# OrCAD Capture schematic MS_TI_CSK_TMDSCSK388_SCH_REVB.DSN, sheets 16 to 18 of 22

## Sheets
16 16.PMIC POWER 1: size C; title: PMIC POWER 1
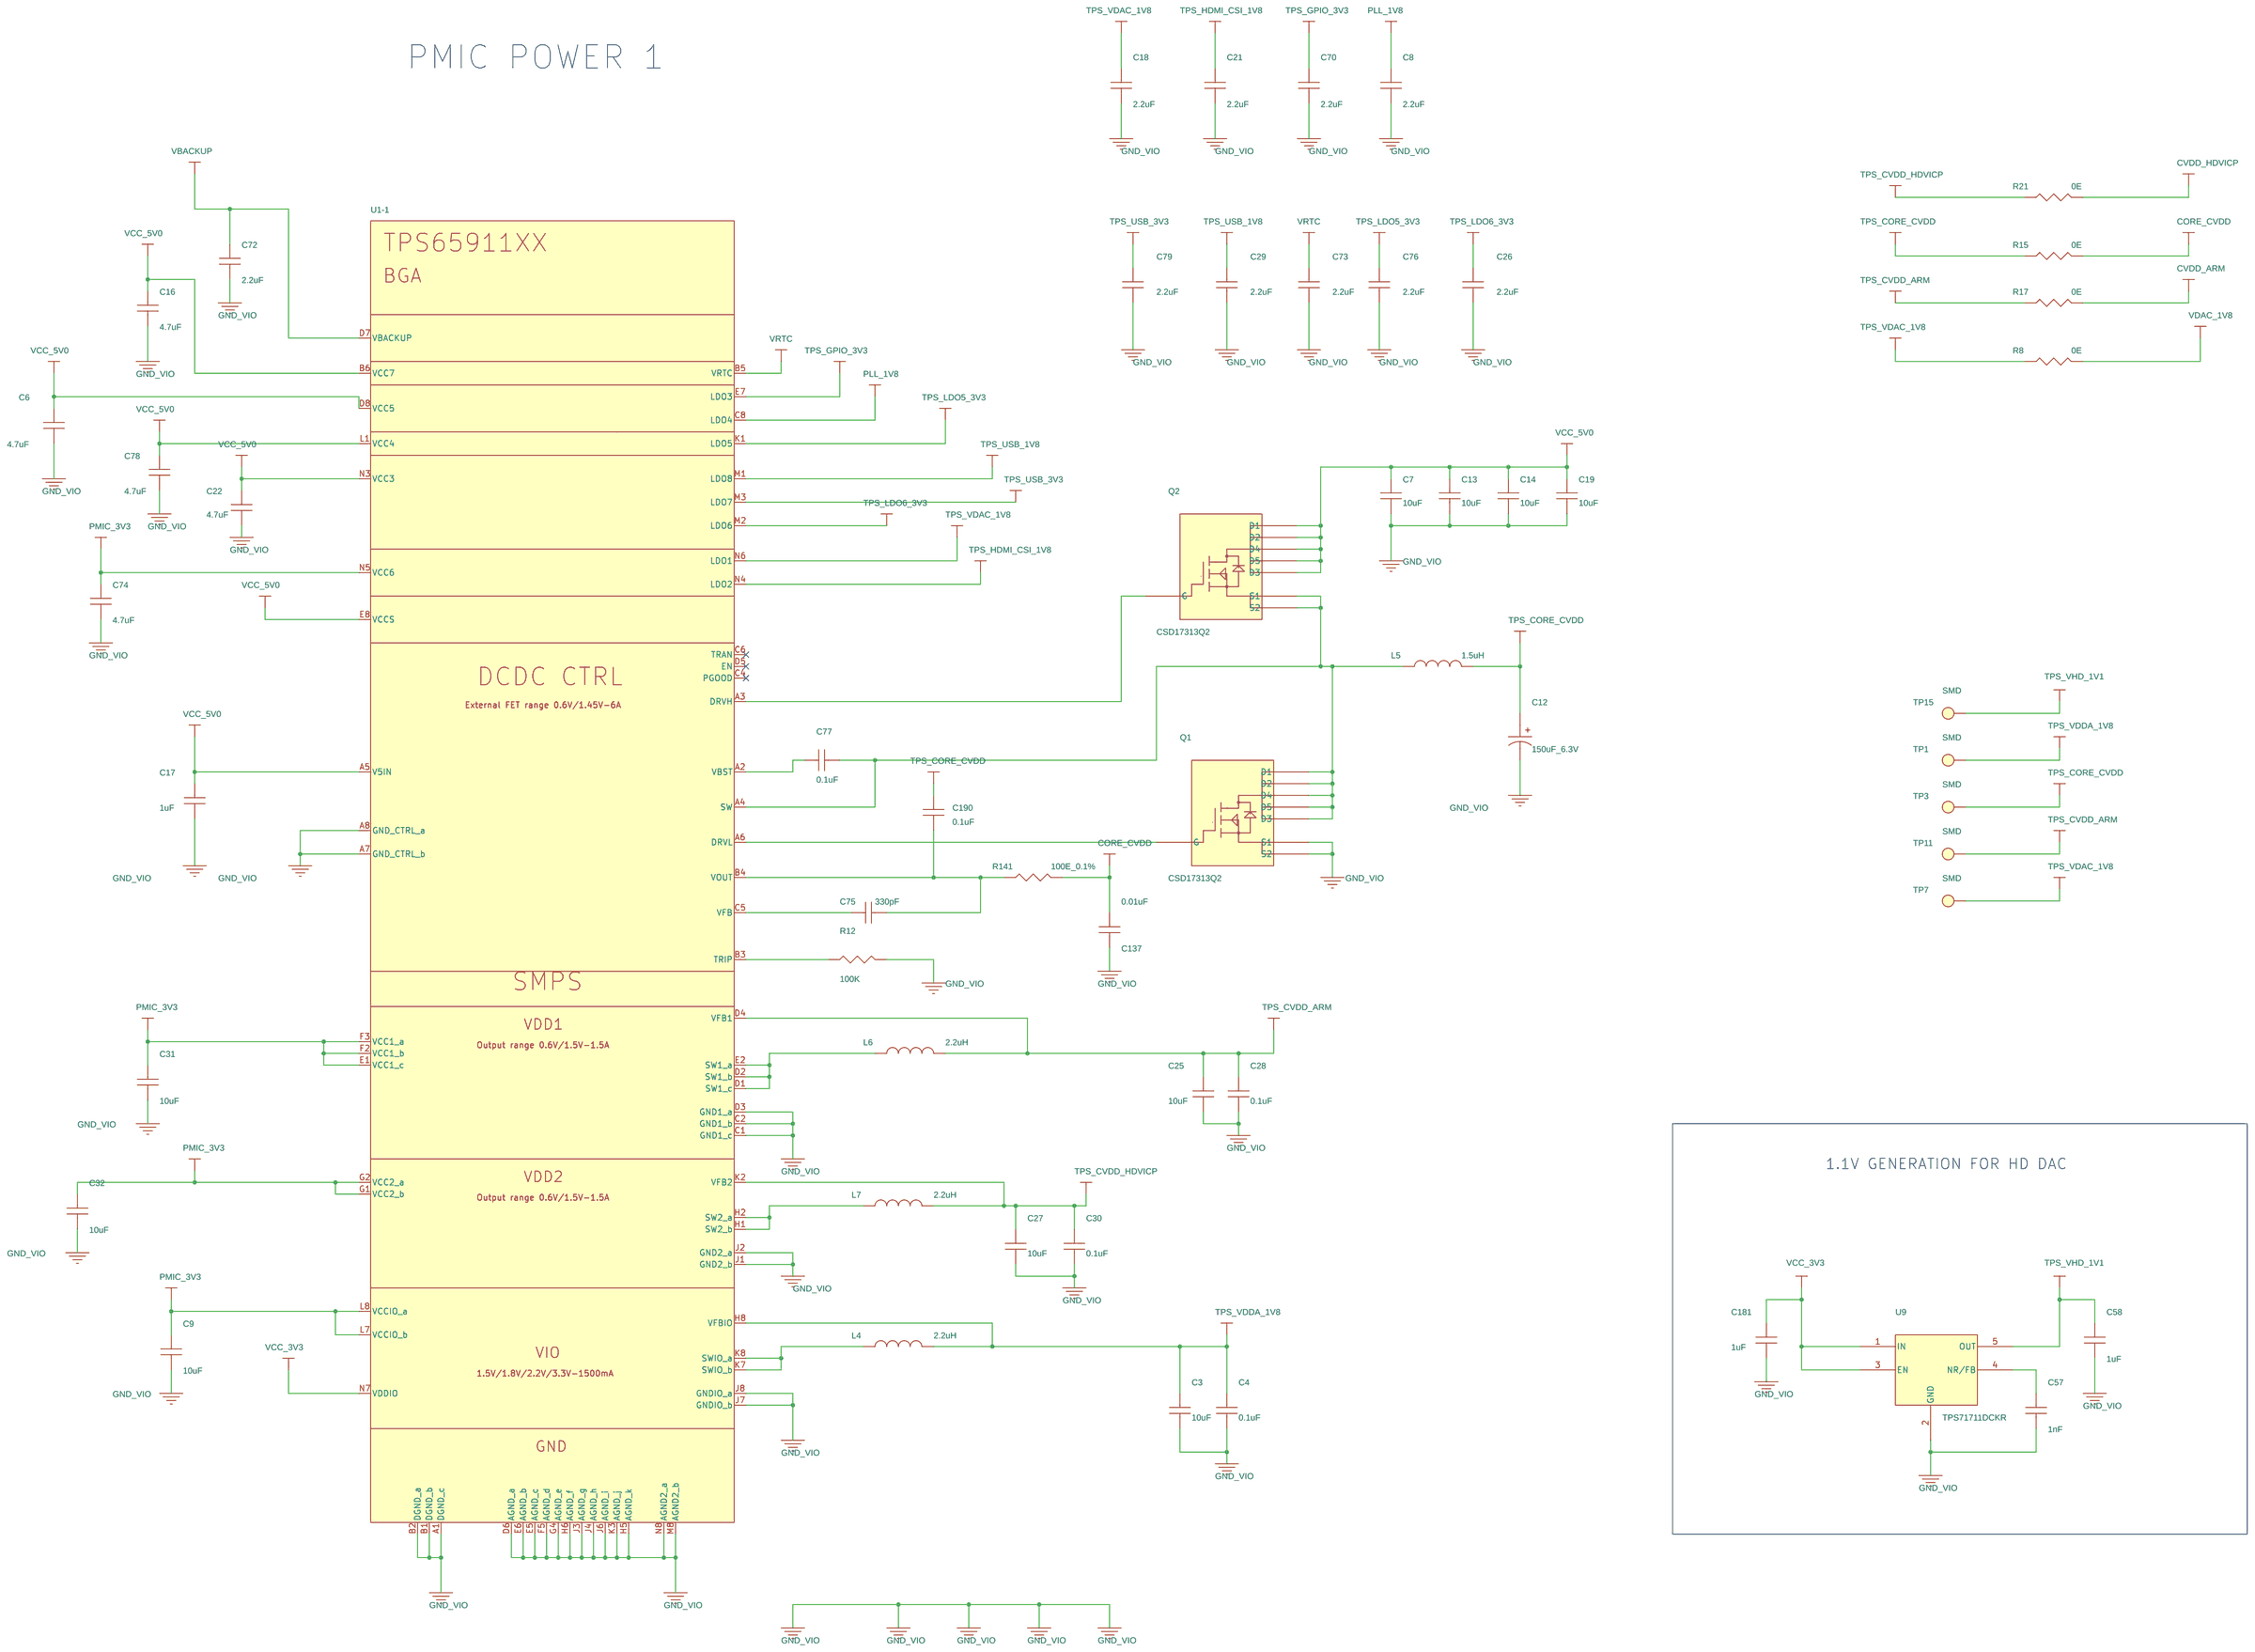
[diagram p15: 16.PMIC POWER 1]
17 17.PMIC POWER 2: size C; title: PMIC POWER 2
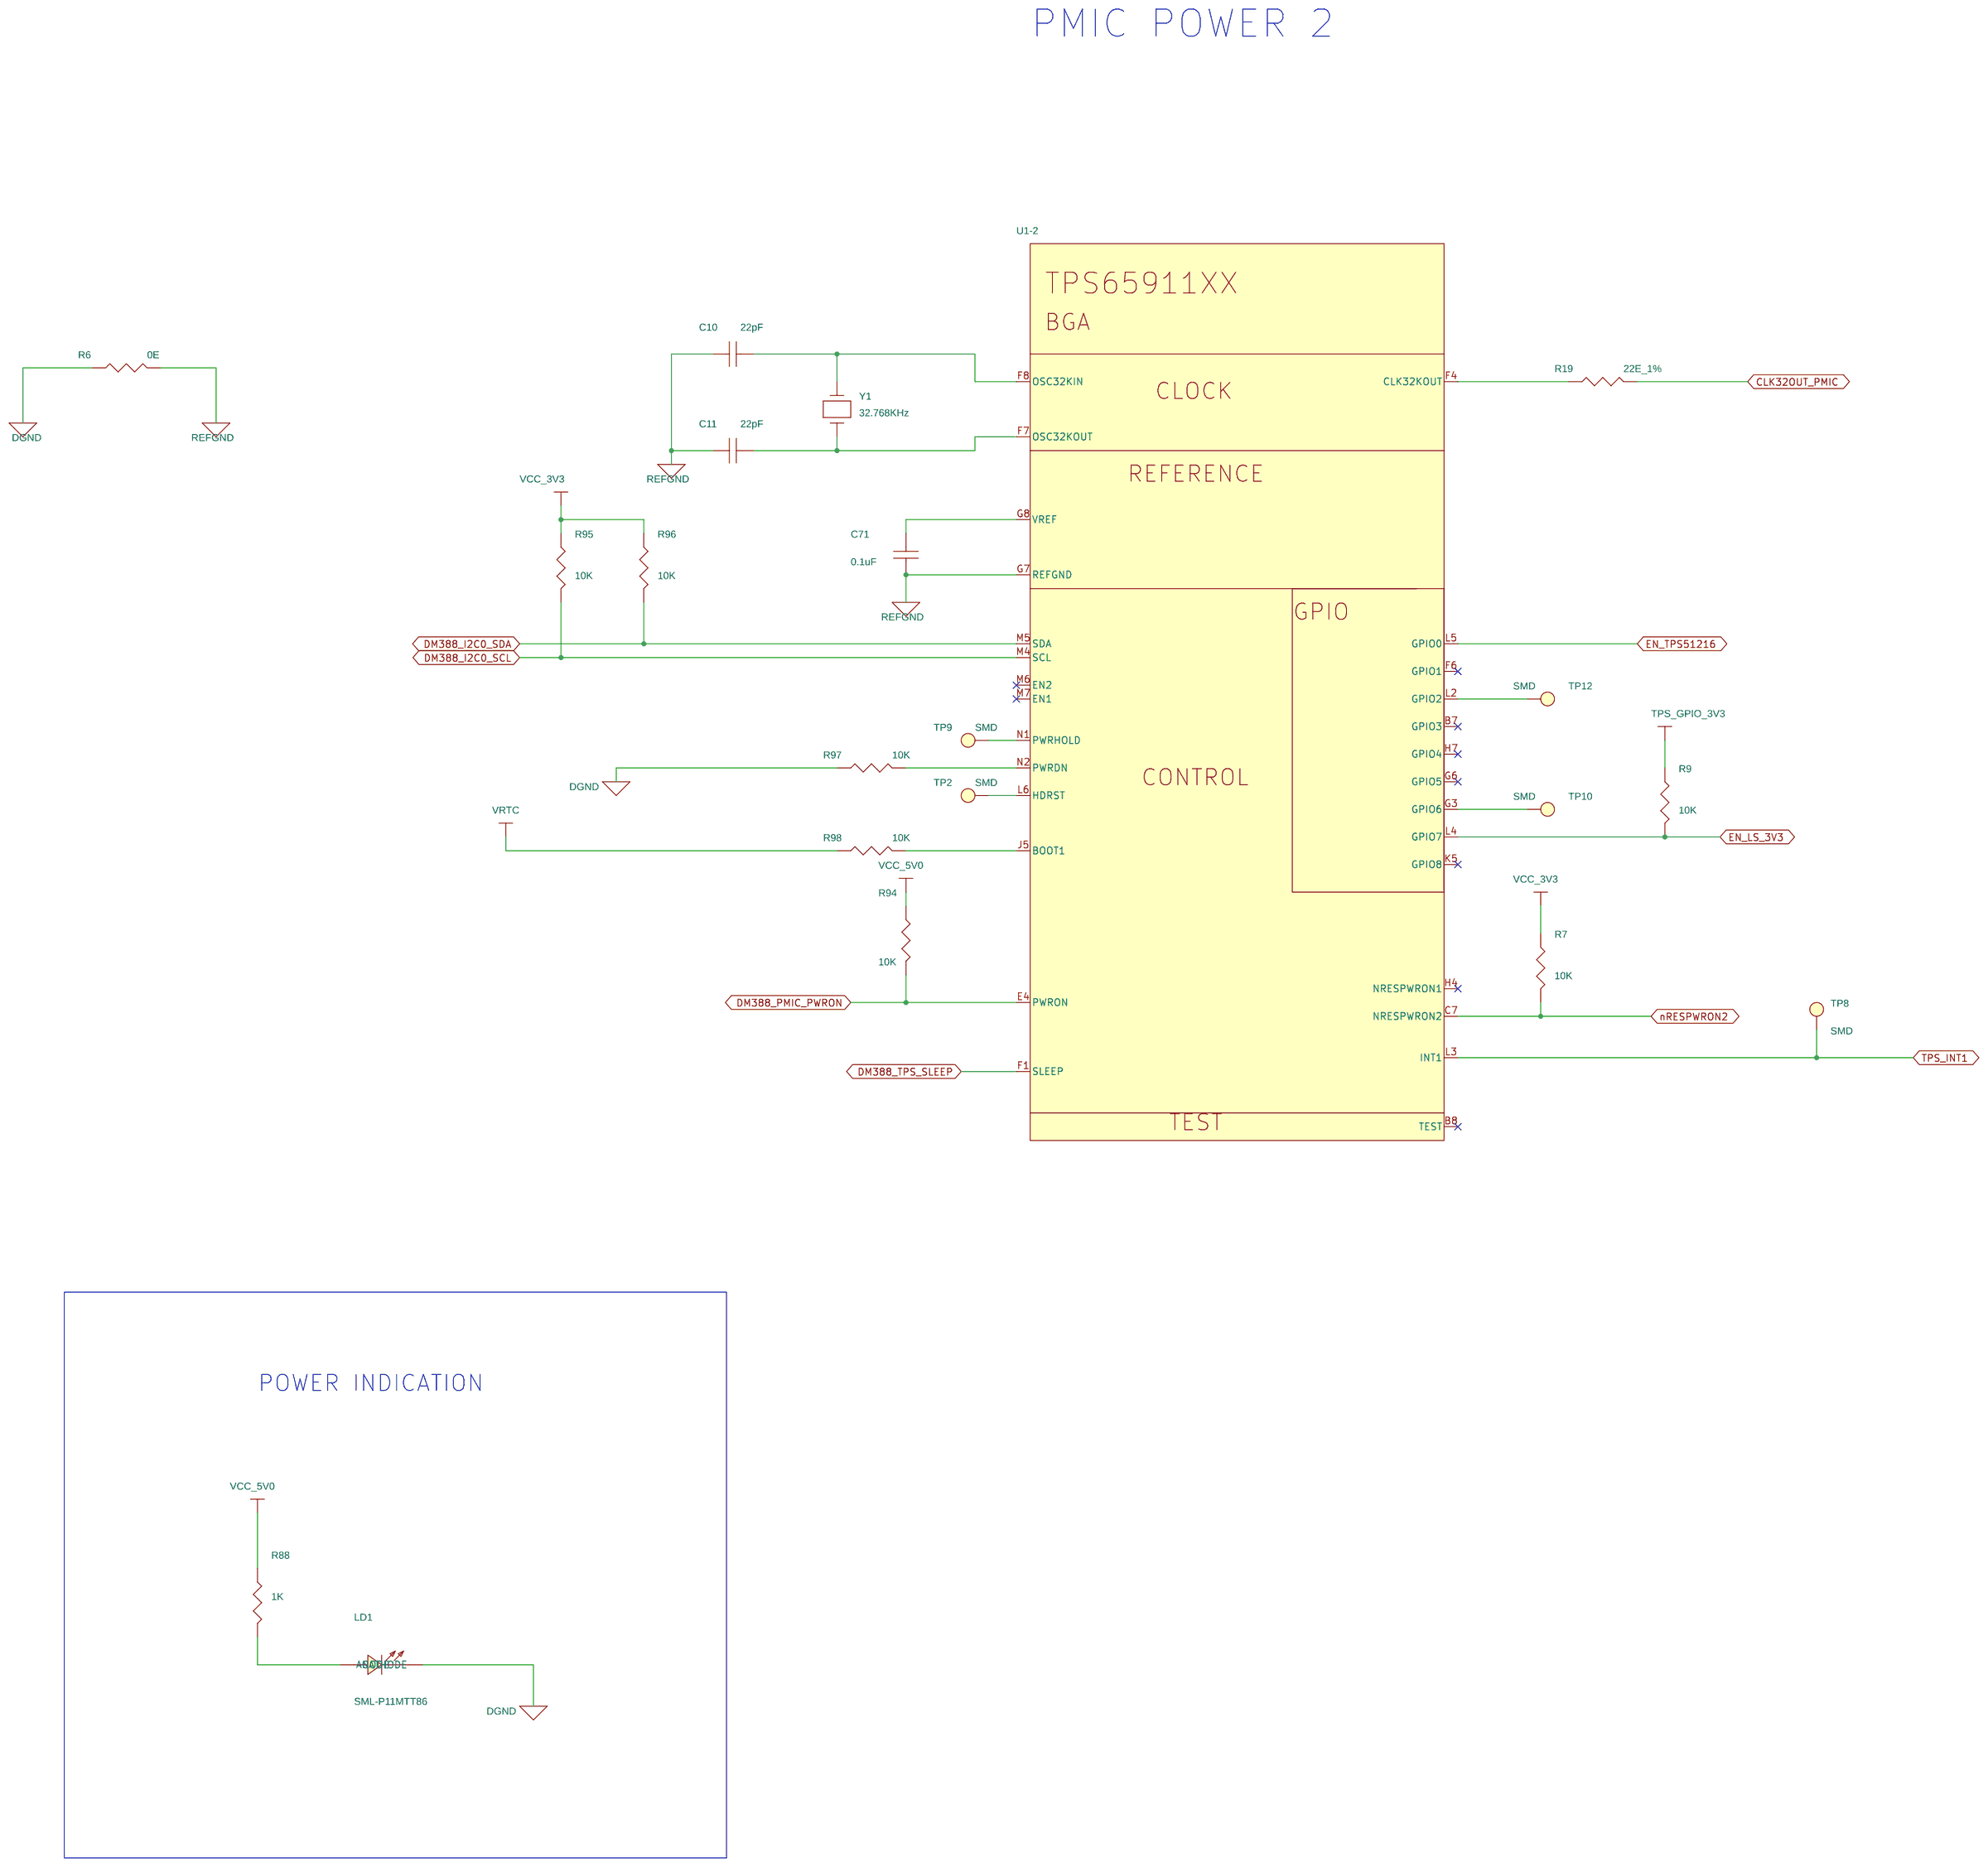
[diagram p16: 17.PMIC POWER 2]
18 18.DDR3 POWER: size C; title: DDR3 POWER
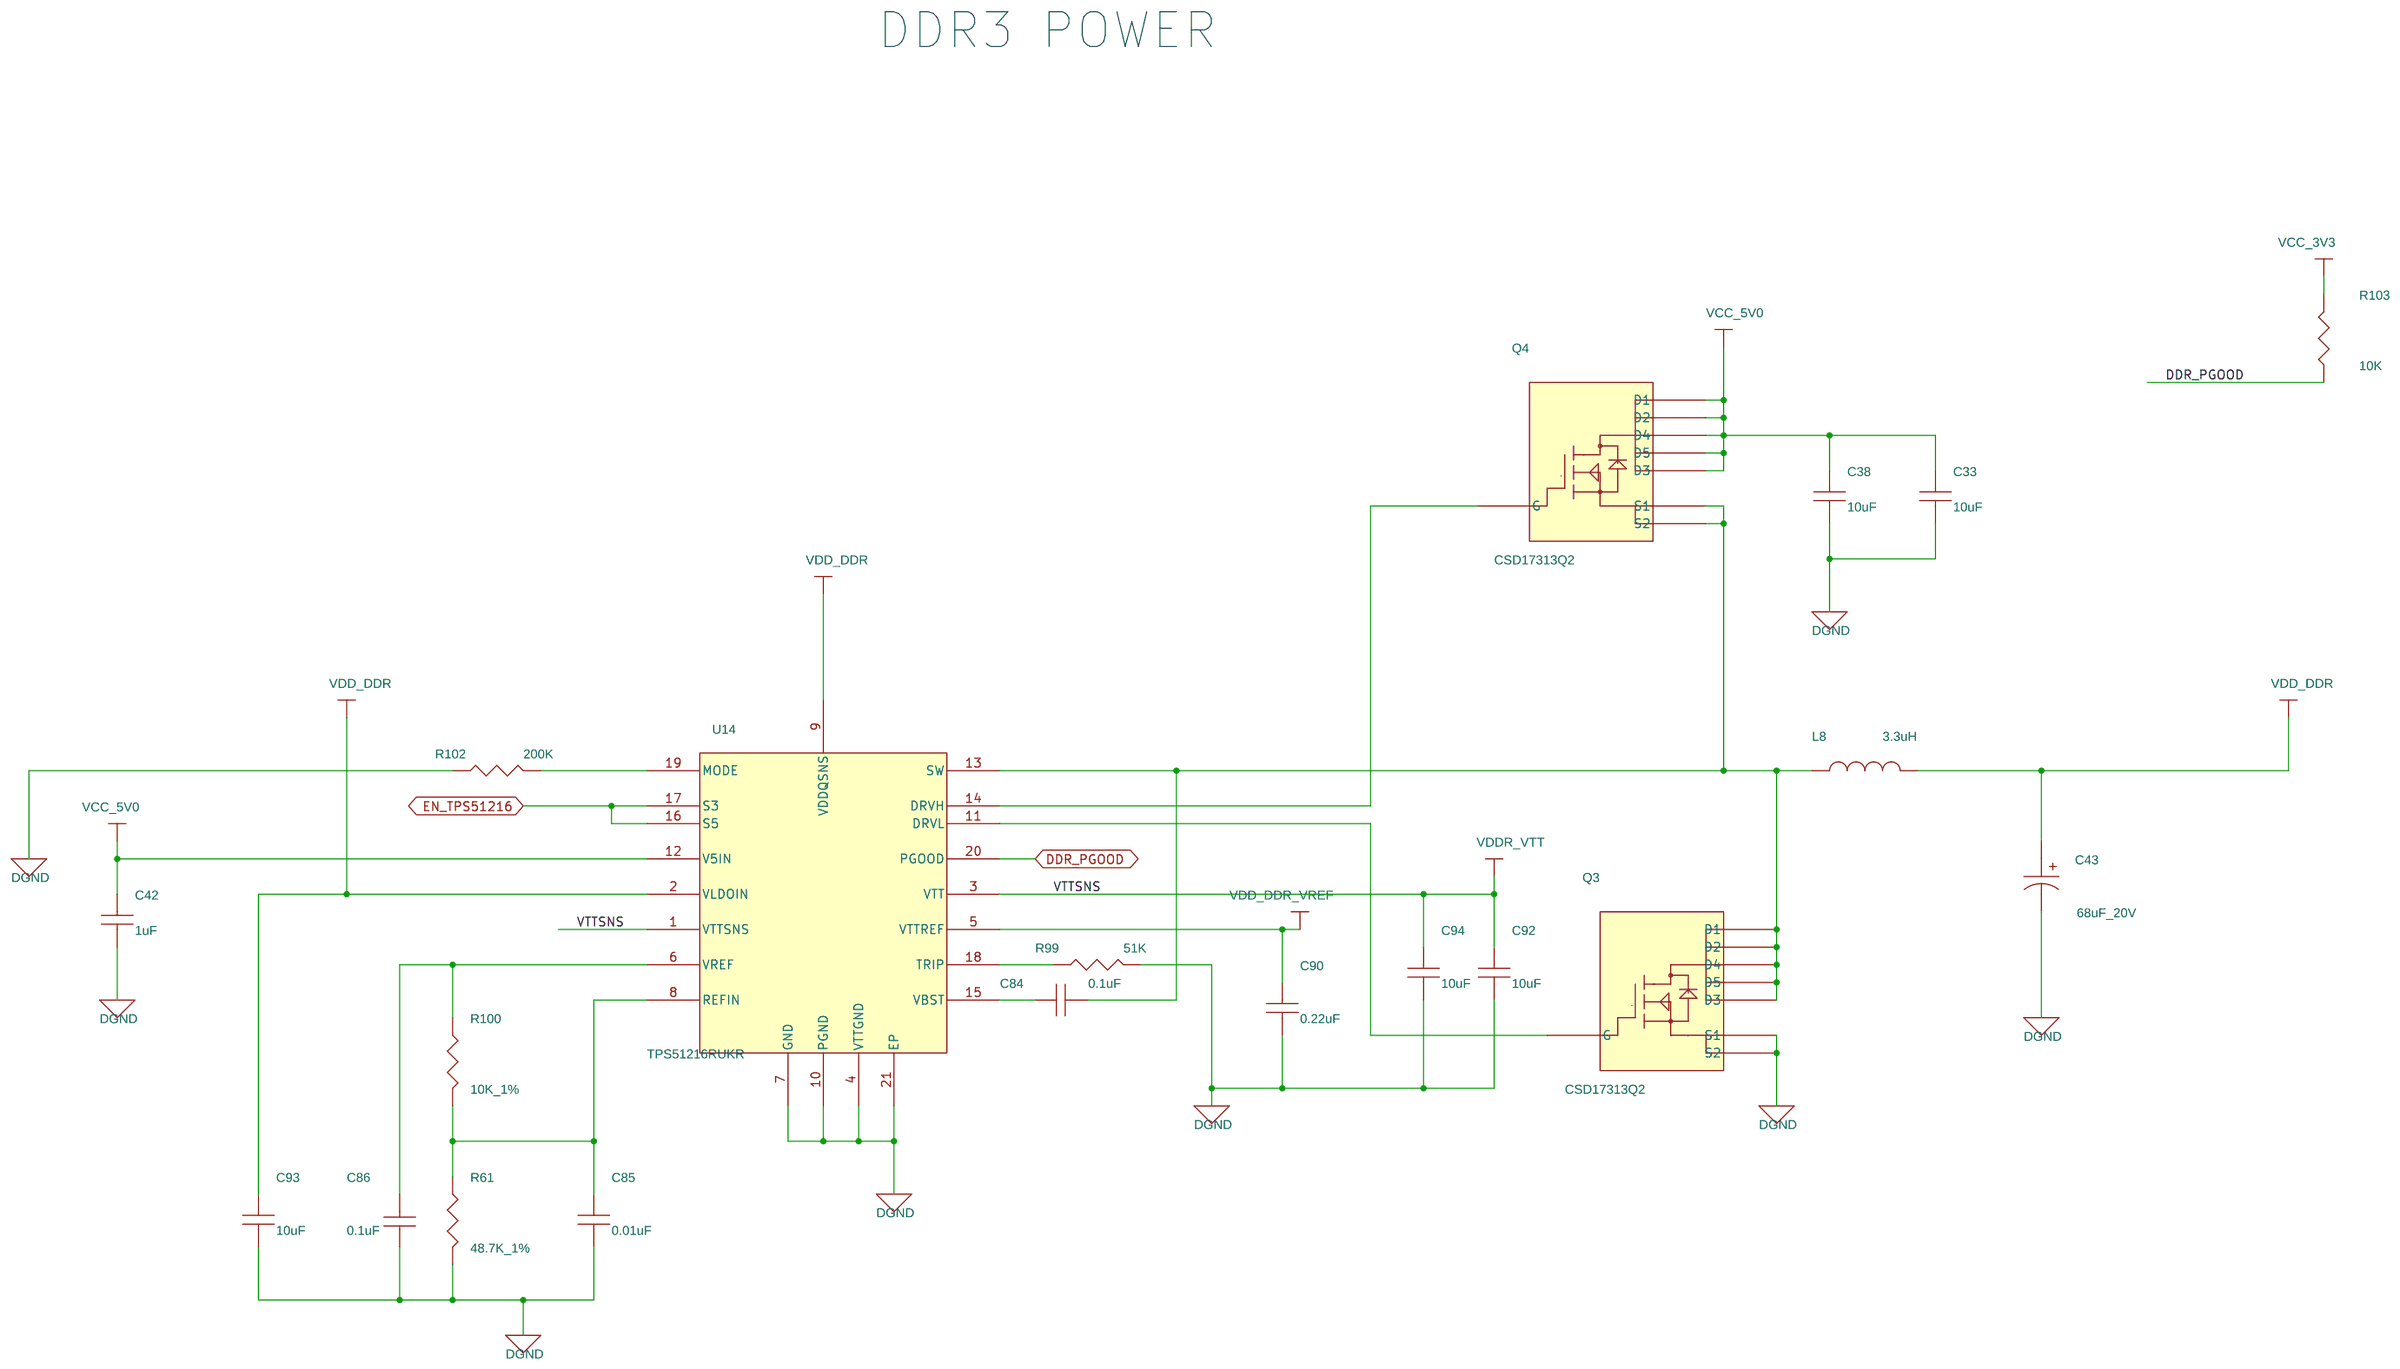
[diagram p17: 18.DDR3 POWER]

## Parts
sheet 16.PMIC POWER 1
C3  10uF  [CAP0402]
C4  0.1uF  [CAP0402]
C6  4.7uF  [CAP0603]
C7  10uF  [CAP0603]
C8  2.2uF  [CAP0402]
C9  10uF  [CAP0603]
C12  150uF_6.3V  [CAPT7343X]
C13  10uF  [CAP0603]
C14  10uF  [CAP0603]
C16  4.7uF  [CAP0603]
C17  1uF  [CAP0603]
C18  2.2uF  [CAP0402]
C19  10uF  [CAP0603]
C21  2.2uF  [CAP0402]
C22  4.7uF  [CAP0603]
C25  10uF  [CAP0402]
C26  2.2uF  [CAP0402]
C27  10uF  [CAP0402]
C28  0.1uF  [CAP0402]
C29  2.2uF  [CAP0402]
C30  0.1uF  [CAP0402]
C31  10uF  [CAP0603]
C32  10uF  [CAP0603]
C57  1nF  [CAP0402]
C58  1uF  [CAP0402]
C70  2.2uF  [CAP0402]
C72  2.2uF  [CAP0603]
C73  2.2uF  [CAP0402]
C74  4.7uF  [CAP0402]
C75  330pF  [CAP0402]
C76  2.2uF  [CAP0402]
C77  0.1uF  [CAP0402]
C78  4.7uF  [CAP0603]
C79  2.2uF  [CAP0402]
C137  0.01uF  [CAP0201]
C181  1uF  [CAP0402]
C190  0.1uF  [CAP0201]
L4  2.2uH  [IND_VLS252012HBX_110X90_SMD]
L5  1.5uH  [IND_XAL4030_170X170_SMD]
L6  2.2uH  [IND_VLS252012HBX_110X90_SMD]
L7  2.2uH  [IND_VLS252012HBX_110X90_SMD]
Q1  CSD17313Q2  [SON6_CSD17313Q2_80X80]
Q2  CSD17313Q2  [SON6_CSD17313Q2_80X80]
R8  0E  [RES0402]
R12  100K  [RES0402]
R15  0E  [RES0805]
R17  0E  [RES0402]
R21  0E  [RES0402]
R141  100E_0.1%  [RES0402]
TP1  SMD  [TP40_SMD]
TP3  SMD  [TP40_SMD]
TP7  SMD  [TP40_SMD]
TP11  SMD  [TP40_SMD]
TP15  SMD  [TP40_SMD]
U1  TPS6591133A2ZRCR  [BGA98_25-59_360x240]  (sections -1,-2)
U9  TPS71711DCKR  [SC70-5]
sheet 17.PMIC POWER 2
C10  22pF  [CAP0402]
C11  22pF  [CAP0402]
C71  0.1uF  [CAP0402]
LD1  SML-P11MTT86  [LED_0402]
R6  0E  [RES0402]
R7  10K  [RES0402]
R9  10K  [RES0402]
R19  22E_1%  [RES0402]
R88  1K  [RES0402]
R94  10K  [RES0402]
R95  10K  [RES0402]
R96  10K  [RES0402]
R97  10K  [RES0402]
R98  10K  [RES0402]
TP2  SMD  [TP40_SMD]
TP8  SMD  [TP40_SMD]
TP9  SMD  [TP40_SMD]
TP10  SMD  [TP40_SMD]
TP12  SMD  [TP40_SMD]
Y1  32.768KHz  [XTAL_9HT10_130X60_SMD]
sheet 18.DDR3 POWER
C33  10uF  [CAP0603]
C38  10uF  [CAP0603]
C42  1uF  [CAP0402]
C43  68uF_20V  [CAPT7343D]
C84  0.1uF  [CAP0402]
C85  0.01uF  [CAP0402]
C86  0.1uF  [CAP0402]
C90  0.22uF  [CAP0402]
C92  10uF  [CAP0402]
C93  10uF  [CAP0402]
C94  10uF  [CAP0402]
L8  3.3uH  [IND_NRS5020_200x200_SMD]
Q3  CSD17313Q2  [SON6_CSD17313Q2_80X80]
Q4  CSD17313Q2  [SON6_CSD17313Q2_80X80]
R61  48.7K_1%  [RES0402]
R99  51K  [RES0402]
R100  10K_1%  [RES0402]
R102  200K  [RES0402]
R103  10K  [RES0402]
U14  TPS51216RUKR  [QFN20_15-74_120X120]

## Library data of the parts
C3 C25 C27 C92-C94 = CAP: CAP CERAMIC 10uF 6.3V 20% X5R 0402; Chkd/date: VASANTHA/120516; Crtd /date: VASANTHA/120516; Custom_Duty: 15%; Customs_HS_Code: 85322990; Distributor_name: DIGIKEY; Distributor_part_number: 1276-1451-1-ND; Height: 0.55MM; Mfr_name: SAMSUNG ELECTRO MECHANIC; Mfr_part_number: CL05A106MQ5NUNC; Mistral Part No: 120014120008-R; Package: 0402; Part_type: CAPACITORS\CERAMIC; Project: TMDXCSK368; RoHS: RoHS; Temperature: -55°C+85°C; Tolerance: 20%; Voltage: 6.3V; Wattage: NA; Weight: NA; Datasheet: Y:\MIS_DATABASE\DATASHEETS\CAPACITORS\CL_SERIES.PDF
C4 C28 C30 C77 C84 C86 = CAP: CAP CERAMIC 0.1uF 16V 10% X7R 0402; Alternate_mfr_name_A: KEMET; Alternate_mfr_part_number_A: C0402C104K4RACT; Chkd/date: MAZHAR/281108; Crtd /date: MAZHAR/030907; Cust_part_number: 1500-80042E; Custom_Duty: 15%; Customs_HS_Code: 85322990; Distributor_name: DIGIKEY; Distributor_name_A: DIGIKEY; Distributor_part_number: 490-3261-1-ND; Distributor_part_number_A: 399-3521-1-ND; Height: 0.55MM; Mfr_name: MURATA; Mfr_part_number: GRM155R71C104KA88D; Mistral Part No: 120009030060-R; Package: 0402; Part_type: CAPACITORS\CERAMIC; Project: SMART VIEW_IP CAMERA; Tolerance: 10%; Voltage: 16V; Wattage: NA; Weight: NA; Datasheet: Y:\MIS_DATABASE\DATASHEETS\CAPACITORS\GRM188SERIES.PDF
C6 C16 C22 C78 = CAP: CAP CERAMIC 4.7uF 16V 10% X5R 0603; Chkd/date: VASANTHA/230714; Crtd /date: BAVISH/060511; Custom_Duty: 15%; Customs_HS_Code: 85322990; Distributor_name: DIGIKEY; Distributor_part_number: 587-2786-1-ND; Height: 0.90MM; Mfr_name: TAIYO YUDEN; Mfr_part_number: EMK107ABJ475KA-T; Mistral Part No: 120011050004-R; Package: 0603; Part_type: CAPACITORS\CERAMIC; Project: HMC; RoHS: RoHS; Temperature: -55°C+85°C; Tolerance: 10%; Voltage: 16V; Wattage: NA; Weight: NA; Datasheet: Y:\MIS_DATABASE\DATASHEETS\CAPACITORS\EMK107.PDF
C7 C13 C14 C19 C33 C38 = CAP: CAP CERAMIC 10uF 16V 20% X5R 0603; Chkd/date: USMAN/060114; Crtd /date: USMAN/151013; Custom_Duty: 15%; Customs_HS_Code: 85322990; Distributor_name: DIGIKEY; Distributor_part_number: 490-7201-1-ND; Height: 0.90MM; Mfr_name: MURATA; Mfr_part_number: GRM188R61C106MA73D; Mistral Part No: 120013100015-R; Package: 0603; Part_type: CAPACITORS\CERAMIC; Project: C-BAND_SYNTH; RoHS: RoHS; Temperature: -55°C+85°C; Tolerance: 20%; Voltage: 16V; Wattage: NA; Weight: NA; Datasheet: Y:\MIS_DATABASE\DATASHEETS\CAPACITORS\GRM188SERIES.PDF
C8 C18 C21 C26 C29 C70 C73 C76 C79 = CAP: CAP CERAMIC 2.2uF 10V 10% X5R 0402; Chkd/date: VASANTHA/120516; Crtd /date: VASANTHA/120516; Custom_Duty: 15%; Customs_HS_Code: 85322990; Distributor_name: DIGIKEY; Distributor_part_number: 1276-1462-1-ND; Height: 0.55MM; Mfr_name: SAMSUNG ELECTRO MECHANIC; Mfr_part_number: CL05A225KP5NNNC; Mistral Part No: 120011100038-R; Package: 0402; Part_type: CAPACITORS\CERAMIC; Project: TMDXCSK368; RoHS: RoHS; Temperature: -55°C+85°C; Tolerance: 10%; Voltage: 10V; Wattage: NA; Weight: NA; Datasheet: Y:\MIS_DATABASE\DATASHEETS\CAPACITORS\CL_SERIES.PDF
C9 C31 C32 = CAP: CAP CERAMIC 10uF 10V 20% X5R 0603; Chkd/date: VASANTHA/120516; Crtd /date: VASANTHA/120516; Custom_Duty: 15%; Customs_HS_Code: 85322990; Distributor_name: DIGIKEY; Distributor_part_number: 490-10475-1-ND; Height: 0.90MM; Mfr_name: MURATA; Mfr_part_number: GRM188R61A106ME69D; Mistral Part No: 120009050022-R; Package: 0603; Part_type: CAPACITORS\CERAMIC; Project: TMDXCSK368; RoHS: RoHS; Temperature: -55°C+85°C; Tolerance: 20%; Voltage: 10V; Wattage: NA; Weight: NA; Datasheet: Y:\MIS_DATABASE\DATASHEETS\CAPACITORS\GRM188SERIES.PDF
C12 = CAP_POL: CAP TANTALUM 150uF 6.3V 20% ESR 15mE D7343; Chkd/date: MAZHAR/230806; Crtd /date: ARAVIND/10/08/06; Custom_Duty: 15%; Customs_HS_Code: 85322990; Distributor_name: DIGIKEY; Distributor_part_number: 399-3055-1-ND; Height: 4.30MM; Mfr_name: KEMET; Mfr_part_number: A700X157M006ATE015; Mistral Part No: 120009030654; Package: D7343; Part_type: CAPACITORS\TANTALUM; Project: PMF BASE CARD; Tolerance: 20%; Voltage: 6.3V; Datasheet: Y:\MIS_DATABASE\DATASHEETS\CAPACITORS\A700X157M006ATE015.PDF
C17 = CAP: CAP CERAMIC 1uF 25V 10% X7R 0603; Chkd/date: VASANTHA/120516; Crtd /date: VASANTHA/120516; Custom_Duty: 15%; Customs_HS_Code: 85322990; Distributor_name: DIGIKEY; Distributor_part_number: 1276-1184-1-ND; Height: 0.90MM; Mfr_name: SAMSUNG ELECTRO MECHANIC; Mfr_part_number: CL10B105KA8NNNC; Mistral Part No: 120011010017-R; Package: 0603; Part_type: CAPACITORS\CERAMIC; Project: TMDXCSK368; RoHS: RoHS; Temperature: -55°C+125°C; Tolerance: 10%; Voltage: 25V; Wattage: NA; Weight: NA; Datasheet: Y:\MIS_DATABASE\DATASHEETS\CAPACITORS\CL_SERIES.PDF
C57 = CAP: CAP CERAMIC 1nF 50V 5% X7R 0402; Chkd/date: BAVISH/100611; Crtd /date: BAVISH/090611; Custom_Duty: 15%; Customs_HS_Code: 85322990; Distributor_name: DIGIKEY; Distributor_part_number: 478-3661-1-ND; Height: 0.60MM; Mfr_name: AVX CORPORATION; Mfr_part_number: 04025C102JAT2A; Mistral Part No: 120011060017-R; Package: 0402; Part_type: CAPACITORS\CERAMIC; Project: CENTAURUS_LCD-ADAPTER; RoHS: RoHS; Temperature: -55°C+125°C; Tolerance: 5%; Voltage: 50V; Wattage: NA; Weight: NA; Datasheet: Y:\MIS_DATABASE\DATASHEETS\CAPACITORS\AVX_MLC.PDF
C42 C58 C181 = CAP: CAP CERAMIC 1uF 10V 10% X5R 0402; Chkd/date: SHREESHAIL/290507; Crtd /date: MAZHAR/290806; Custom_Duty: 15%; Customs_HS_Code: 85322990; Distributor_name: DIGIKEY; Distributor_part_number: 490-3890-1-ND; Height: 0.55MM; Mfr_name: MURATA; Mfr_part_number: GRM155R61A105KE15D; Mistral Part No: 120009030264; Package: 0402; Part_type: CAPACITORS\CERAMIC; Project: SVDO_RMB_MMA; Tolerance: 10%; Voltage: 10V; Datasheet: Y:\MIS_DATABASE\DATASHEETS\CAPACITORS\GRM188SERIES.PDF
C72 = CAP: CAP CERAMIC 2.2uF 16V 10% X5R 0603; Chkd/date: VASANTHA/120516; Crtd /date: VASANTHA/120516; Custom_Duty: 15%; Customs_HS_Code: 85322990; Distributor_name: DIGIKEY; Distributor_part_number: 490-3296-1-ND; Height: 0.90MM; Mfr_name: MURATA; Mfr_part_number: GRM188R61C225KE15D; Mistral Part No: 120009050002-R; Package: 0603; Part_type: CAPACITORS\CERAMIC; Project: TMDXCSK368; RoHS: RoHS; Temperature: -55°C+85°C; Tolerance: 10%; Voltage: 16V; Wattage: NA; Weight: NA; Datasheet: Y:\MIS_DATABASE\DATASHEETS\CAPACITORS\GRM188SERIES.PDF
C74 = CAP: CAP CERAMIC 4.7uF 10V 10% X5R 0402; Chkd/date: VASANTHA/171014; Crtd /date: NAVEED/200814; Custom_Duty: 15%; Customs_HS_Code: 85322990; Distributor_name: DIGIKEY; Distributor_part_number: 445-13820-1-ND; Height: 0.55MM; Mfr_name: TDK CORPORATION; Mfr_part_number: C1005X5R1A475K050BC; Mistral Part No: 120014080006-R; Package: 0402; Part_type: CAPACITORS\CERAMIC; Project: HUMANWARE PHONEIX; RoHS: RoHS; Temperature: -55°C+85°C; Tolerance: 10%; Voltage: 10V; Wattage: NA; Weight: NA; Datasheet: Y:\MIS_DATABASE\DATASHEETS\CAPACITORS\C1005X5R1A475M.PDF
C75 = CAP: CAP CERAMIC 330pF 50V 5% NP0 0402; Chkd/date: SHREESHAIL/290507; Crtd /date: MAZHAR/221206; Custom_Duty: 15%; Customs_HS_Code: 85322990; Distributor_name: DIGIKEY; Distributor_part_number: 490-1295-1-ND; Height: 0.55MM; Mfr_name: MURATA; Mfr_part_number: GRM1555C1H331JA01D; Mistral Part No: 120009030375; Package: 0402; Part_type: CAPACITORS\CERAMIC; Project: ADR1B; Tolerance: 5%; Voltage: 50V; Datasheet: Y:\MIS_DATABASE\DATASHEETS\CAPACITORS\GRM188SERIES.PDF
C137 = CAP: CAP CERAMIC 0.01uF 10V 10% X7R 0201; Chkd/date: MAZHAR/301208; Crtd /date: MAZHAR/080306; Cust_part_number: 1500-80097E; Custom_Duty: 15%; Customs_HS_Code: 85322990; Distributor_name: DIGIKEY; Distributor_part_number: 490-3194-1-ND; Height: 0.33MM; Mfr_name: MURATA; Mfr_part_number: GRM033R71A103KA01D; Mistral Part No: 120009030029-R; Package: 0201; Part_type: CAPACITORS\CERAMIC; Project: J32; RoHS: RoHS; Tolerance: 10%; Voltage: 10V; Datasheet: Y:\MIS_DATABASE\DATASHEETS\CAPACITORS\GRM033.PDF
C190 = CAP: CAP CERAMIC 0.1uF 10V 20% X5R 0201; Chkd/date: RAGESH/290910; Crtd /date: MUDDU/290410; Custom_Duty: 15%; Customs_HS_Code: 85322990; Distributor_name: DIGIKEY; Distributor_part_number: 490-5405-1-ND; Height: 0.33MM; Mfr_name: MURATA; Mfr_part_number: GRM033R61A104ME15D; Mistral Part No: 120010040004-R; Package: 0201; Part_type: CAPACITORS\CERAMIC; Project: BUG_BASE-II; RoHS: RoHS; Temperature: -55°C+85°C; Tolerance: 20%; Voltage: 10V; Weight: NA; Datasheet: Y:\MIS_DATABASE\DATASHEETS\CAPACITORS\MURATA_CMCC.PDF
L4 L6 L7 = INDUCTOR: IND POWER 2.2uH 2.3A 20% SMD; Chkd/date: VASANTHA/250516; Crtd /date: VASANTHA/250516; Custom_Duty: 24%; Customs_HS_Code: 85437099; Distributor_name: DIGIKEY; Distributor_part_number: 445-173027-1-ND; Height: 1.20MM; Mfr_name: TDK CORPORATION; Mfr_part_number: VLS252012HBX-2R2M-1; Mistral Part No: 130016050036-R; Package: SMD; Project: TMDXCSK388; RoHS: RoHS; Temperature: -40°C+105°C; Tolerance: 20%; Voltage: NA; Wattage: NA; Weight: NA; Datasheet: Y:\MIS_DATABASE\DATASHEETS\DISCRETES\INDUCTORS\VLS252012HBX.PDF
L5 = INDUCTOR: IND POWER 1.5uH 20% 7.5A SMD; Chkd/date: JEBRAN/060815; Crtd /date: JEBRAN/060815; Cust_part_number: 1800-80031E; Custom_Duty: 24%; Customs_HS_Code: 85437099; Distributor_name: MOUSER; Distributor_part_number: 994-XAL4020-152MEB; Height: 4.10MM; Mfr_name: COILCARFT; Mfr_part_number: XAL4020-152MEB; Mistral Part No: 130015080007-R; Package: SMD; Project: OCTASIC; RoHS: RoHS; Temperature: -40°C+125°C; Tolerance: 20%; Voltage: NA; Wattage: NA; Weight: 0.37g; Datasheet: Y:\MIS_DATABASE\DATASHEETS\DISCRETES\INDUCTORS\XAL4020.PDF
Q1-Q4 = MOSFET_CSD17313Q2: IC MOSFET N-CHANNEL SON6; Chkd/date: VASANTHA/291214; Crtd /date: NAVEED/110914; Custom_Duty: 15%; Customs_HS_Code: 85423100; Distributor_name: DIGIKEY; Distributor_part_number: 296-27233-1-ND; Height: 0.85MM; Mfr_name: TEXAS INSTRUMENTS; Mistral Part No: 142014090005-R; Package: SON6; Part_type: ICS\POWER\MOSFET; Project: ZK_BIOMETRIC; RoHS: RoHS; Temperature: -55°C+150°C; Tolerance: NA; Voltage: NA; Wattage: NA; Weight: NA; Datasheet: Y:\MIS_DATABASE\DATASHEETS\DISCRETES\TRANSISTORS_FETS\CSD17313Q2.PDF
R8 R17 R21 = RESISTOR: RES 0E 1/16W 5% 0402; Chkd/date: USMAN240712; Crtd /date: CHAITHANYA/300911; Custom_Duty: 15%; Customs_HS_Code: 85332119; Distributor_name: DIGIKEY; Distributor_part_number: 311-0.0JRCT-ND; Height: 0.40MM; Mfr_name: YAGEO; Mfr_part_number: RC0402JR-070RL; Mistral Part No: 110011090036-R; Package: 0402; Part_type: RESISTORS\FIXED; Project: VP-4000-PROCESSOR; RoHS: RoHS; SIGNAL_MODEL: RESISTOR_RES0402_0E_0E; Temperature: -55°C+155°C; Tolerance: 5%; Voltage: NA; Wattage: 1/16W; Weight: NA; Datasheet: Y:\MIS_DATABASE\DATASHEETS\RESISTORS\YAGEO_RC0402JR.PDF
R12 = RESISTOR: RES 100K 1/16W 5% 0402; Chkd/date: VASANTHA/130516; Crtd /date: VASANTHA/130516; Custom_Duty: 15%; Customs_HS_Code: 85332119; Distributor_name: DIGIKEY; Distributor_part_number: A121521CT-ND; Height: 0.40MM; Mfr_name: TE CONNECTIVITY; Mfr_part_number: CRG0402J100K/10; Mistral Part No: 110011060002-R; Package: 0402; Part_type: RESISTORS\FIXED; Project: TMDXCSK368; RoHS: RoHS; Temperature: -55°C+125°C; Tolerance: 5%; Voltage: NA; Wattage: 1/16W; Weight: NA; Datasheet: Y:\MIS_DATABASE\DATASHEETS\RESISTORS\CRG-SERIES.PDF
R15 = R: RES 0E 1/8W 5% 0805; Alternate_mfr_name_B: PANASONIC-ECG-ECG; Alternate_mfr_part_number_B: ERJ-6GEY0R00V; Chkd/date: MAZHAR/170709; Crtd /date: MAZHAR/181007; Cust_part_number: 4700-00000E; Custom_Duty: 15%; Customs_HS_Code: 85332119; Distributor_name: DIGIKEY; Distributor_name_B: DIGIKEY; Distributor_part_number: RHM0.0ACT-ND; Distributor_part_number_B: P0.0ACT-ND; Height: 0.70MM; Mfr_name: ROHM; Mfr_part_number: MCR10EZHJ000; Mistral Part No: 110009030074-R; Package: 0805; Part_type: RESISTORS\FIXED; Project: SD_WATERLOO; RoHS: RoHS; Tolerance: 5%; Wattage: 1/8W; Datasheet: Y:\MIS_DATABASE\DATASHEETS\RESISTORS\MCR10.PDF
R141 = RESISTOR: RES 100E 1/16W 0.1% 0402; Chkd/date: SUHAS/290910; Crtd /date: MUDDU/020910; Custom_Duty: 15%; Customs_HS_Code: 85332119; Distributor_name: DIGIKEY; Distributor_part_number: TNP100DACT-ND; Height: 0.40MM; Mfr_name: VISHAY; Mfr_part_number: TNPW0402100RBEED; Mistral Part No: 110010090013-P; Package: 0402; Part_type: RESISTORS\FIXED; Project: FLR PSPU; RoHS: Pb-Free; Temperature: -55°C+125°C; Tolerance: 0.1%; Voltage: 25V; Wattage: 1/16W; Weight: 0.65g/1000pcs; Datasheet: Y:\MIS_DATABASE\DATASHEETS\RESISTORS\VISHAY_TNPW_0.1%.PDF
TP1-TP3 TP7-TP12 TP15 = TESTPOINT: TESTPOINT 40 SMD; Chkd/date: MAZHAR/190505; Crtd /date: MAZHAR/190505; Distributor_name: NA; Distributor_part_number: NA; Height: NA; Mfr_name: LOCAL; Mistral Part No: 130009030933; Part_type: MISC\TESTPOINT; Project: RAINIER-3
U1 = TPS659113A2_BGA98: IC POWER MANAGEMENT BGA98; Chkd/date: VASANTHA/170516; Crtd /date: VASANTHA/170516; Custom_Duty: 15%; Customs_HS_Code: 85423100; Distributor_name: DIGIKEY; Distributor_part_number: 296-40911-1-ND; Height: 1.00MM; Mfr_name: TEXAS INSTRUMENTS; Mistral Part No: 142016050010-R; Package: BGA98; Part_type: ICS\POWER; Project: TMDXCSK388; RoHS: RoHS; Temperature: -40°C+85°C; Tolerance: NA; Voltage: NA; Wattage: NA; Weight: NA; Color: Default; Location X-Coordinate: 0; Location Y-Coordinate: 0; Power Pins Visible: False; Primitive: DEFAULT; Datasheet: Y:\MIS_DATABASE\DATASHEETS\ICS\POWER\TPS659113-SER.PDF
U9 = TPS71711DCKR_SC70-5: IC LINEAR REGULATOR LDO 150mA SC70-5; Chkd/date: Not Chkd; Crtd /date: BAVISH/160811; Custom_Duty: 15%; Customs_HS_Code: 85423100; Distributor_name: DIGIKEY; Distributor_part_number: 296-23172-1-ND; Height: 1.10MM; Mfr_name: TEXAS INSTRUMENTS; Mistral Part No: 142011080011-R; Part_type: ICS\POWER\VOLTAGE REGULATOR; Project: DM385EVM_BASE-BOARD; RoHS: RoHS; Temperature: -40°C+125°C; Tolerance: NA; Voltage: NA; Wattage: NA; Weight: NA; Datasheet: Y:\MIS_DATABASE\DATASHEETS\ICS\POWER\TPS71711.PDF
C10 C11 = CAP: CAP CERAMIC 22pF 50V 5% NP0 0402; Alternate_mfr_name_A: AVX CORPORATION; Alternate_mfr_name_C: PANASONIC-ECG; Alternate_mfr_name_D: MURATA; Alternate_mfr_part_number_A: 04025A220JAT2A; Alternate_mfr_part_number_C: ECJ-0EC1H220J; Alternate_mfr_part_number_D: GRM1555C1H220JZ01D; Chkd/date: SHREESHAIL/301105; Crtd /date: MAZHAR/040505; Custom_Duty: 15%; Customs_HS_Code: 85322990; Distributor_name: DIGIKEY; Distributor_name_A: DIGIKEY; Distributor_name_C: DIGIKEY; Distributor_name_D: DIGIKEY; Distributor_part_number: 399-1015-1-ND; Distributor_part_number_A: 478-1074-1-ND; Distributor_part_number_C: PCC220CQCT-ND; Distributor_part_number_D: 490-1283-1-ND; Height: 0.55MM; Mfr_name: KEMET; Mfr_part_number: C0402C220J5GACTU; Mistral Part No: 120009030327-R; Package: 0402; Part_type: CAPACITORS\CERAMIC; Project: G4_SVGA; RoHS: RoHS; Tolerance: 5%; Voltage: 50V; Datasheet: Y:\MIS_DATABASE\DATASHEETS\CAPACITORS\KEMET-C08.PDF
C71 = CAP: CAP CERAMIC 0.1uF 25V -20% TO +80 Y5V 0402; Chkd/date: SHREESHAIL/301105; Crtd /date: MAZHAR/251005; Custom_Duty: 15%; Customs_HS_Code: 85322990; Distributor_name: DIGIKEY; Distributor_part_number: 490-3271-1-ND; Height: 0.55MM; Mfr_name: MURATA; Mfr_part_number: GRM155F51E104ZA01D; Mistral Part No: 120009030085; Package: 0402; Part_type: CAPACITORS\CERAMIC; Project: ADR; Tolerance: -20% TO +80%; Voltage: 25V; Datasheet: Y:\MIS_DATABASE\DATASHEETS\CAPACITORS\GRM188SERIES.PDF
LD1 = DIODE_LED: DIODE LED GREEN 0402; Chkd/date: RAVI/181010; Crtd /date: MUDDU/190610; Custom_Duty: 24%; Customs_HS_Code: 85439000; Distributor_name: DIGIKEY; Distributor_part_number: 511-1652-1-ND; Height: 0.25MM; Mfr_name: ROHM; Mistral Part No: 130010060029-R; Package: 0402; Part_type: OPTO\LED; Project: XMC660; RoHS: RoHS; Temperature: -40°C+85°C; Weight: NA; Datasheet: Y:\MIS_DATABASE\DATASHEETS\DISCRETES\LEDS\SML-P11.PDF
R6 = RESISTOR: RES 0E 1/10W 5% 0402; Chkd/date: NAVEED/241114; Crtd /date: NAVEED/201014; Custom_Duty: 15%; Customs_HS_Code: 85332119; Distributor_name: DIGIKEY; Distributor_part_number: P0.0JCT-ND; Height: 0.40MM; Mfr_name: PANASONIC-ECG; Mfr_part_number: ERJ-2GE0R00X; Mistral Part No: 110014100008-R; Package: 0402; Part_type: RESISTORS\FIXED; Project: AEGIS POM; RoHS: RoHS; SIGNAL_MODEL: RESISTOR_RES0402_0E_0E; Tolerance: 5%; Wattage: 1/10W; Datasheet: Y:\MIS_DATABASE\DATASHEETS\RESISTORS\ERJ12.PDF
R7 R9 R94-R98 R103 = RESISTOR: RES 10K 1/16W 5% 0402; Alternate_mfr_name_A: AVX CORPORATION; Alternate_mfr_name_B: PANASONIC-ECG-ECG; Alternate_mfr_name_C: YAGEO AMERICA; Alternate_mfr_name_D: WALSIN; Alternate_mfr_part_number_A: CR05-103J-H; Alternate_mfr_part_number_B: ERJ-2GEJ103X; Alternate_mfr_part_number_C: 9C04021A1002JLHF3; Alternate_mfr_part_number_D: WR04X103_JT; Chkd/date: SHREESHAIL/061205; Crtd /date: MAZHAR/230805; Custom_Duty: 15%; Customs_HS_Code: 85332119; Distributor_name: DIGIKEY; Distributor_name_A: MOUSER; Distributor_name_B: DIGIKEY; Distributor_name_C: DIGIKEY; Distributor_name_D: NA; Distributor_part_number: 311-10KJRCT-ND; Distributor_part_number_A: 581-CR051002JT; Distributor_part_number_B: P10KJCT-ND; Distributor_part_number_C: 311-10KJCT-ND; Distributor_part_number_D: NA; Height: 0.40MM; Mfr_name: YAGEO AMERICA; Mfr_part_number: RC0402JR-0710KL; Mistral Part No: 110009030208-P; Package: 0402; Part_type: RESISTORS\FIXED; Project: HSE; RoHS: Pb-Free; Tolerance: 5%; Wattage: 1/16W; Datasheet: Y:\MIS_DATABASE\DATASHEETS\RESISTORS\YAGEO-RC0402.PDF
R19 = RESISTOR: RES 22E 1/16W 1% 0402; Alternate_mfr_name_A: VISHAY; Alternate_mfr_part_number_A: CRCW040222R0FKED; Chkd/date: SUHAS/290910; Crtd /date: MAZHAR/090909; Cust_part_number: 4700-80047E; Custom_Duty: 15%; Customs_HS_Code: 85332119; Distributor_name: DIGIKEY; Distributor_name_A: DIGIKEY; Distributor_part_number: 311-22.0LRCT-ND; Distributor_part_number_A: 541-22.0LCT-ND; Height: 0.40MM; Mfr_name: YAGEO AMERICA; Mfr_part_number: RC0402FR-0722RL; Mistral Part No: 110009090004-P; Package: 0402; Part_type: RESISTORS\FIXED; Project: VMEFMCD; Remarks: In alternate datasheet it is RoHS COMPLIANT. Y:\MIS_DATABASE\DATASHEETS\RESISTORS\CRCW0402.PDF; RoHS: Pb-Free; Temperature: -55°C+155°C; Tolerance: 1%; Voltage: 50V; Wattage: 1/16W; Weight: 0.8g/1000pcs; Datasheet: Y:\MIS_DATABASE\DATASHEETS\RESISTORS\YAGEO-RC0402.PDF
R88 = RESISTOR: RES 1K 1/16W 5% 0402; Chkd/date: VASANTHA/120516; Crtd /date: VASANTHA/120516; Custom_Duty: 15%; Customs_HS_Code: 85332119; Distributor_name: DIGIKEY; Distributor_part_number: 311-1.0KJRCT-ND; Height: 0.40MM; Mfr_name: YAGEO AMERICA; Mfr_part_number: RC0402JR-071KL; Mistral Part No: 110010070006-R; Package: 0402; Part_type: RESISTORS\FIXED; Project: TMDXCSK368; RoHS: RoHS; Temperature: -55°C+155°C; Tolerance: 5%; Voltage: NA; Wattage: 1/16W; Weight: NA; Datasheet: Y:\MIS_DATABASE\DATASHEETS\RESISTORS\YAGEO-RC0402.PDF
Y1 = CRY: CRY 32.768KHz SMD; Chkd/date: VASANTHA/130516; Crtd /date: VASANTHA/130516; Custom_Duty: 24%; Customs_HS_Code: 85439000; Distributor_name: DIGIKEY; Distributor_part_number: 887-1504-1-ND; Height: 0.85MM; Mfr_name: TXC CORPORATION; Mfr_part_number: 9HT10-32.768KDZF-T; Mistral Part No: 130016050023-R; Package: SMD; Part_type: CRYSTAL; Project: TMDXCSK368; RoHS: RoHS; Temperature: -40°C+85°C; Tolerance: NA; Voltage: NA; Wattage: NA; Weight: NA; Datasheet: Y:\MIS_DATABASE\DATASHEETS\MISC\CRY_OSC\9HT10.PDF
C43 = CAP_POL: CAP TANTALUM 68uF 20V 10% D7343; Chkd/date: JAGADISH/280314; Crtd /date: SARANYA/270314; Custom_Duty: 15%; Customs_HS_Code: 85322990; Distributor_name: DIGIKEY; Distributor_part_number: 399-3803-1-ND; Height: 3.10MM; Mfr_name: KEMET; Mfr_part_number: T491D686K020AT; Mistral Part No: 120014030031-R; Package: D7343; Part_type: CAPACITORS\TANTALUM; Project: DMP; RoHS: RoHS; Temperature: -55°C+125°C; Tolerance: 10%; Voltage: 20V; Wattage: NA; Weight: NA; Datasheet: Y:\MIS_DATABASE\DATASHEETS\CAPACITORS\KEMETTANTALUMT491.PDF
C85 = CAP: CAP CERAMIC 10000pF 10V 10% X7R 0402; Chkd/date: VASANTHA/120516; Crtd /date: VASANTHA/120516; Custom_Duty: 15%; Customs_HS_Code: 85322990; Distributor_name: DIGIKEY; Distributor_part_number: 1276-1502-1-ND; Height: 0.55MM; Mfr_name: SAMSUNG ELECTRO MECHANIC; Mfr_part_number: CL05B103KP5NNNC; Mistral Part No: 120016050007-R; Package: 0402; Part_type: CAPACITORS\CERAMIC; Project: TMDXCSK368; RoHS: RoHS; Temperature: -55°C+125°C; Tolerance: 10%; Voltage: 10V; Wattage: NA; Weight: NA; Datasheet: Y:\MIS_DATABASE\DATASHEETS\CAPACITORS\CL_SERIES.PDF
C90 = CAP: CAP CERAMIC 0.22uF 10V 10% X5R 0402; Chkd/date: VASANTHA/120516; Crtd /date: VASANTHA/120516; Custom_Duty: 15%; Customs_HS_Code: 85322990; Distributor_name: DIGIKEY; Distributor_part_number: 1276-1457-1-ND; Height: 0.55MM; Mfr_name: SAMSUNG ELECTRO MECHANIC; Mfr_part_number: CL05A224KP5NNWC; Mistral Part No: 120009030090-R; Package: 0402; Part_type: CAPACITORS\CERAMIC; Project: TMDXCSK368; RoHS: RoHS; Temperature: -55°C+85°C; Tolerance: 10%; Voltage: 10V; Wattage: NA; Weight: NA; Datasheet: Y:\MIS_DATABASE\DATASHEETS\CAPACITORS\CL_SERIES.PDF
L8 = INDUCTOR: IND 3.3uH 3A 20% SMD; Chkd/date: VASANTHA/310516; Crtd /date: VASANTHA/310516; Custom_Duty: 24%; Customs_HS_Code: 85437099; Distributor_name: DIGIKEY; Distributor_part_number: 587-3459-1-ND; Height: 3.10MM; Mfr_name: TAIYO YUDEN; Mfr_part_number: NRS5030T3R3MMGJ; Mistral Part No: 130016050050-R; Package: SMD; Project: TMDXCSK388; RoHS: RoHS; Temperature: -25°C+120°C; Tolerance: 20%; Voltage: NA; Wattage: NA; Weight: NA; Datasheet: Y:\MIS_DATABASE\DATASHEETS\DISCRETES\INDUCTORS\NRX_SERIES.PDF
R61 = RESISTOR: RES 48.7K 1/10W 1% 0402; Chkd/date: SUHAS/270910; Crtd /date: MAZHAR/110210; Custom_Duty: 15%; Customs_HS_Code: 85332119; Distributor_name: DIGIKEY; Distributor_part_number: P48.7KLCT-ND; Height: 0.40MM; Mfr_name: PANASONIC-ECG; Mfr_part_number: ERJ-2RKF4872X; Mistral Part No: 110010020013-R; Package: 0402; Part_type: RESISTORS\FIXED; Project: KOPIN_MODULS; RoHS: RoHS; Temperature: -55°C+125°C; Tolerance: 1%; Voltage: 100V; Wattage: 1/10W; Weight: 0.8g/1000pcs; Datasheet: Y:\MIS_DATABASE\DATASHEETS\RESISTORS\PAN-ERJSERIES.PDF
R99 = RESISTOR: RES 51K 1/16W 5% 0402; Chkd/date: VASANTHA/130516; Crtd /date: VASANTHA/130516; Custom_Duty: 15%; Customs_HS_Code: 85332119; Distributor_name: DIGIKEY; Distributor_part_number: 311-51KJRCT-ND; Height: 0.55MM; Mfr_name: YAGEO AMERICA; Mfr_part_number: RC0402JR-0751KL; Mistral Part No: 110009030966-R; Package: 0402; Part_type: RESISTORS\FIXED; Project: TMDXCSK368; RoHS: RoHS; Temperature: -55°C+155°C; Tolerance: 5%; Voltage: NA; Wattage: 1/16W; Weight: NA; Datasheet: Y:\MIS_DATABASE\DATASHEETS\RESISTORS\YAGEO-RC0402.PDF
R100 = RESISTOR: RES 10K 1/16W 1% 0402; Alternate_mfr_name_A: AVX CORPORATION; Alternate_mfr_name_B: PANASONIC-ECG-ECG; Alternate_mfr_name_C: YAGEO AMERICA; Alternate_mfr_name_D: VISHAY; Alternate_mfr_part_number_A: CR05-103F-H; Alternate_mfr_part_number_B: ERJ-2RKF1002X; Alternate_mfr_part_number_C: 9C04021A1002FLHF3; Alternate_mfr_part_number_D: CRCW040210K0FKED; Chkd/date: SHREESHAIL/310506; Crtd /date: GEETHA/290506; Custom_Duty: 15%; Customs_HS_Code: 85332119; Distributor_name: DIGIKEY; Distributor_name_A: NA; Distributor_name_B: DIGIKEY; Distributor_name_C: DIGIKEY; Distributor_name_D: DIGIKEY; Distributor_part_number: 311-10.0KLRTR-ND; Distributor_part_number_A: NA; Distributor_part_number_B: P10.0KLCT-ND; Distributor_part_number_C: 311-10.0KLCT-ND; Distributor_part_number_D: 541-10.0KLCT-ND; Height: 0.40MM; Mfr_name: YAGEO AMERICA; Mfr_part_number: RC0402FR-0710KL; Mistral Part No: 110009030220-P; Package: 0402; Part_type: RESISTORS\FIXED; Project: VOCERA; RoHS: Pb-Free; Tolerance: 1%; Wattage: 1/16W; Datasheet: Y:\MIS_DATABASE\DATASHEETS\RESISTORS\YAGEO-RC0402.PDF
R102 = RESISTOR: RES 200K 1/16W 5% 0402; Chkd/date: SUHAS/290910; Crtd /date: MAZHAR/051109; Custom_Duty: 15%; Customs_HS_Code: 85332119; Distributor_name: DIGIKEY; Distributor_part_number: 311-200KJRCT-ND; Height: 0.40MM; Mfr_name: YAGEO AMERICA; Mfr_part_number: RC0402JR-07200KL; Mistral Part No: 110009110002-P; Package: 0402; Part_type: RESISTORS\FIXED; Project: GEACOM_PHRAZER; RoHS: Pb-Free; Temperature: -55°C+155°C; Tolerance: 5%; Voltage: 50V; Wattage: 1/16W; Weight: 0.8g/1000pcs; Datasheet: Y:\MIS_DATABASE\DATASHEETS\RESISTORS\YAGEO-RC0402.PDF
U14 = TPS51216RUKR_QFN20: IC DDR2,3,3L MEMORY SYNCHRONOUS BUCK CONTROLLER QFN20; Chkd/date: VASANTHA/240516; Crtd /date: VASANTHA/240516; Custom_Duty: 15%; Customs_HS_Code: 85423100; Distributor_name: DIGIKEY; Distributor_part_number: 296-38296-1-ND; Height: 0.80MM; Mfr_name: TEXAS INSTRUMENTS; Mistral Part No: 142016050013-R; Package: QFN20; Part_type: ICS\POWER\VOLTAGE REGULATOR; Project: TMDXCSK8127; RoHS: RoHS; Temperature: -40°C+85°C; Tolerance: NA; Voltage: NA; Wattage: NA; Weight: NA; Datasheet: Y:\MIS_DATABASE\DATASHEETS\MISC\REGULATORS\TPS51216RUKR.PDF

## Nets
DGND: C3.2 C4.2 C6.2 C7.2 C8.2 C9.2 C12.2 C13.2 C14.2 C16.2 C17.2 C18.2 C19.2 C21.2 C22.2 C25.2 C26.2 C27.2 C28.2 C29.2 C30.2 C31.2 C32.2 C33.2 C38.2 C42.2 C43.2 C57.2 C58.2 C70.2 C72.2 C73.2 C74.2 C76.2 C78.2 C79.2 C85.2 C86.1 C90.2 C92.2 C93.2 C94.2 C137.2 C181.2 LD1.1(CATHODE) Q1.4(S1) Q1.7(S2) Q3.4(S1) Q3.7(S2) R6.1 R12.2 R61.2 R97.1 R99.2 R102.1 U1.A1(DGND_c) U1.A7(GND_CTRL_b) U1.A8(GND_CTRL_a) U1.B1(DGND_b) U1.B2(DGND_a) U1.C1(GND1_c) U1.C2(GND1_b) U1.D3(GND1_a) U1.D6(AGND_a) U1.E5(AGND_c) U1.E6(AGND_b) U1.F5(AGND_d) U1.G4(AGND_e) U1.H5(AGND_k) U1.H6(AGND_f) U1.J1(GND2_b) U1.J2(GND2_a) U1.J3(AGND_g) U1.J4(AGND_h) U1.J6(AGND_i) U1.J7(GNDIO_b) U1.J8(GNDIO_a) U1.K3(AGND_j) U1.M8(AGND2_b) U1.N8(AGND2_a) U9.2(GND) U14.4(VTTGND) U14.7(GND) U14.10(PGND) U14.21(EP) ; also on sheet 9 10 11 12 13 14 15 19 20 21
VCC_3V3: C181.1 R7.1 R95.1 R96.1 R103.1 U1.N7(VDDIO) U9.1(IN) U9.3(EN) ; also on sheet 9 10 12 13 14 19 21 22
VCC_5V0: C6.1 C7.1 C13.1 C14.1 C16.1 C17.1 C19.1 C22.1 C33.1 C38.1 C42.1 C78.1 Q2.1(D1) Q2.2(D2) Q2.5(D3) Q2.6(D4) Q2.8(D5) Q4.1(D1) Q4.2(D2) Q4.5(D3) Q4.6(D4) Q4.8(D5) R88.1 R94.1 U1.A5(V5IN) U1.B6(VCC7) U1.D8(VCC5) U1.E8(VCCS) U1.L1(VCC4) U1.N3(VCC3) U14.12(V5IN) ; also on sheet 21
VDD_DDR: C43.1 C93.1 L8.2 U14.2(VLDOIN) U14.9(VDDQSNS) ; also on sheet 11 14
VDD_DDR_VREF: C90.1 U14.5(VTTREF) ; also on sheet 11
VDDR_VTT: C92.1 C94.1 U14.1(VTTSNS) U14.3(VTT) ; also on sheet 11
CLK32OUT_PMIC: R19.2 ; also on sheet 12
CORE_CVDD: C137.1 R15.2 R141.2 ; also on sheet 14
CVDD_ARM: R17.2 ; also on sheet 14
CVDD_HDVICP: R21.2 ; also on sheet 14
DDR_PGOOD: R103.2 U14.20(PGOOD) ; also on sheet 9
DM388_I2C0_SCL: R95.2 U1.M4(SCL) ; also on sheet 22
DM388_I2C0_SDA: R96.2 U1.M5(SDA) ; also on sheet 22
DM388_PMIC_PWRON: R94.2 U1.E4(PWRON) ; also on sheet 21
DM388_TPS_SLEEP: U1.F1(SLEEP) ; also on sheet 10
EN_LS_3V3: R9.2 U1.L4(GPIO7) ; also on sheet 21
EN_TPS51216: U1.L5(GPIO0) U14.16(S5) U14.17(S3)
nRESPWRON2: R7.2 U1.C7(NRESPWRON2) ; also on sheet 9
PLL_1V8: C8.1 U1.C8(LDO4) ; also on sheet 14
PMIC_3V3: C9.1 C31.1 C32.1 C74.1 U1.E1(VCC1_c) U1.F2(VCC1_b) U1.F3(VCC1_a) U1.G1(VCC2_b) U1.G2(VCC2_a) U1.L7(VCCIO_b) U1.L8(VCCIO_a) U1.N5(VCC6) ; also on sheet 21
REFGND: C10.1 C11.1 C71.1 R6.2 U1.G7(REFGND)
TPS_CORE_CVDD: C12.1 C190.1 L5.2 R15.1 TP3.1(TP)
TPS_CVDD_ARM: C25.1 C28.1 L6.2 R17.1 TP11.1(TP) U1.D4(VFB1)
TPS_CVDD_HDVICP: C27.1 C30.1 L7.2 R21.1 U1.K2(VFB2)
TPS_GPIO_3V3: C70.1 R9.1 U1.E7(LDO3)
TPS_HDMI_CSI_1V8: C21.1 U1.N4(LDO2) ; also on sheet 14
TPS_INT1: TP8.1(TP) U1.L3(INT1) ; also on sheet 9 21
TPS_LDO5_3V3: C76.1 U1.K1(LDO5)
TPS_LDO6_3V3: C26.1 U1.M2(LDO6)
TPS_USB_1V8: C29.1 U1.M1(LDO8) ; also on sheet 14
TPS_USB_3V3: C79.1 U1.M3(LDO7) ; also on sheet 14
TPS_VDAC_1V8: C18.1 R8.1 TP7.1(TP) U1.N6(LDO1)
TPS_VDDA_1V8: C3.1 C4.1 L4.2 TP1.1(TP) U1.H8(VFBIO) ; also on sheet 12 13 14 21
TPS_VHD_1V1: C58.1 TP15.1(TP) U9.5(OUT) ; also on sheet 14
VBACKUP: C72.1 U1.D7(VBACKUP) ; also on sheet 21
VDAC_1V8: R8.2 ; also on sheet 14
VRTC: C73.1 R98.1 U1.B5(VRTC)
N11847334: L6.1 U1.D1(SW1_c) U1.D2(SW1_b) U1.E2(SW1_a)
N11848351: L7.1 U1.H1(SW2_b) U1.H2(SW2_a)
N11848810: L4.1 U1.K7(SWIO_b) U1.K8(SWIO_a)
N12909578: C11.2 U1.F7(OSC32KOUT) Y1.1
N12909638: C10.2 U1.F8(OSC32KIN) Y1.2
N12910002: C71.2 U1.G8(VREF)
N12911225: R97.2 U1.N2(PWRDN)
N12911351: R98.2 U1.J5(BOOT1)
N12971691: R12.1 U1.B3(TRIP)
N12971710: C75.1 U1.C5(VFB)
N12972021: C75.2 C190.2 R141.1 U1.B4(VOUT)
N12972241: Q2.3(G) U1.A3(DRVH)
N12972253: Q1.3(G) U1.A6(DRVL)
N12973009: C77.1 U1.A2(VBST)
N12973023: C77.2 L5.1 Q1.1(D1) Q1.2(D2) Q1.5(D3) Q1.6(D4) Q1.8(D5) Q2.4(S1) Q2.7(S2) U1.A4(SW)
N14066974: Q3.3(G) U14.11(DRVL)
N14067031: Q4.3(G) U14.14(DRVH)
N14067125: C84.2 L8.1 Q3.1(D1) Q3.2(D2) Q3.5(D3) Q3.6(D4) Q3.8(D5) Q4.4(S1) Q4.7(S2) U14.13(SW)
N14068093: R99.1 U14.18(TRIP)
N14068298: C85.1 R61.1 R100.2 U14.8(REFIN)
N14068467: C86.2 R100.1 U14.6(VREF)
N14068656: R102.2 U14.19(MODE)
N14068754: C84.1 U14.15(VBST)
N14162633: C57.1 U9.4(NR/FB)
N14445231: TP9.1(TP) U1.N1(PWRHOLD)
N14486422: LD1.2(ANODE) R88.2
N14554807: TP12.1(TP) U1.L2(GPIO2)
N14554839: TP10.1(TP) U1.G3(GPIO6)
N14645029: TP2.1(TP) U1.L6(HDRST)
N14719275: R19.1 U1.F4(CLK32KOUT)

Not connected (* = marked no-connect by the designer): U1 B7(GPIO3)* B8(TEST)* C4(PGOOD)* C6(TRAN)* D5(EN)* F6(GPIO1)* G6(GPIO5)* H4(NRESPWRON1)* H7(GPIO4)* K5(GPIO8)* M6(EN2)* M7(EN1)*

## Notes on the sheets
sheet 16
- PMIC POWER 1
- 1.1V GENERATION FOR HD DAC
sheet 17
- PMIC POWER 2
- POWER INDICATION
sheet 18
- DDR3 POWER
